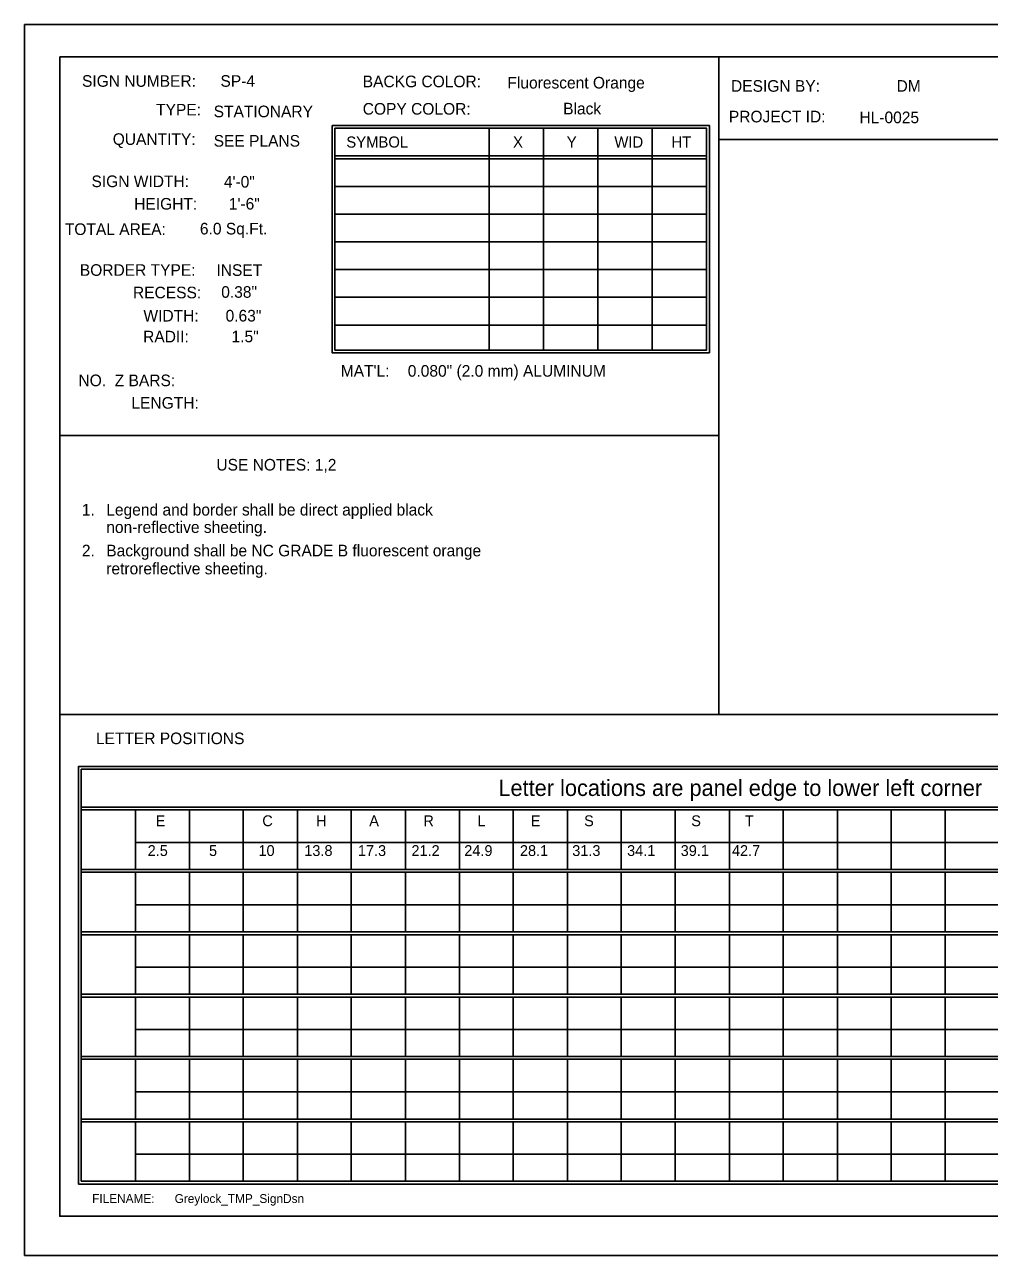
# Model space of a CAD drawing. Extents: x 1788.1 to 1851.2, y 237.2 to 283.4.
# Drawn here: x 1821.02 to 1837.36, y 237.17 to 258.03 of the extents above; entities that cross this region are included whole.
import ezdxf

# ---------------------------------------------------------------- set-up
doc = ezdxf.new("R2010")
doc.units = 0
for name, color, linetype in [('Old_Level_2', 7, 'Continuous'), ('Old_Level_3', 7, 'Continuous'), ('Old_Level_7', 7, 'Continuous'), ('Sheet Plot Border Outside CELL', 7, 'Continuous')]:
    doc.layers.add(name, color=color, linetype=linetype)

msp = doc.modelspace()

# ---------------------------------------------------------------- linework, layer by layer
at = {"layer": 'Old_Level_2'}
for p, q in [((1832.78, 257.479), (1832.78, 246.338)), ((1828.894, 256.27), (1828.894, 252.512)), ((1829.814, 256.27), (1829.814, 252.512)), ((1830.734, 256.27), (1830.734, 252.512)), ((1831.654, 256.27), (1831.654, 252.512)), ((1832.78, 256.081), (1849.944, 256.081)), ((1826.278, 255.8), (1832.575, 255.8)), ((1826.278, 255.754), (1832.575, 255.754)), ((1826.278, 255.284), (1832.575, 255.284)), ((1826.278, 254.814), (1832.575, 254.814)), ((1826.278, 254.344), (1832.575, 254.344)), ((1826.278, 253.875), (1832.575, 253.875)), ((1826.278, 253.405), (1832.575, 253.405)), ((1826.278, 252.935), (1832.575, 252.935)), ((1832.78, 251.061), (1821.618, 251.061)), ((1821.618, 246.338), (1832.78, 246.338)), ((1832.78, 246.338), (1849.944, 246.338)), ((1821.981, 244.765), (1843.759, 244.765)), ((1821.981, 244.719), (1843.759, 244.719)), ((1822.9, 244.719), (1822.9, 243.709)), ((1823.818, 244.719), (1823.818, 243.709)), ((1824.727, 244.719), (1824.727, 243.709)), ((1825.645, 244.719), (1825.645, 243.709)), ((1826.554, 244.719), (1826.554, 243.709)), ((1827.472, 244.719), (1827.472, 243.709)), ((1828.39, 244.719), (1828.39, 243.709)), ((1829.299, 244.719), (1829.299, 243.709)), ((1830.218, 244.719), (1830.218, 243.709)), ((1831.126, 244.719), (1831.126, 243.709)), ((1832.045, 244.719), (1832.045, 243.709)), ((1832.963, 244.719), (1832.963, 243.709)), ((1833.872, 244.719), (1833.872, 243.709)), ((1834.79, 244.719), (1834.79, 243.709)), ((1835.699, 244.719), (1835.699, 243.709)), ((1836.617, 244.719), (1836.617, 243.709)), ((1822.9, 244.168), (1843.759, 244.168)), ((1821.981, 243.709), (1843.759, 243.709)), ((1821.981, 243.663), (1843.759, 243.663)), ((1822.9, 243.663), (1822.9, 242.652)), ((1823.818, 243.663), (1823.818, 242.652)), ((1824.727, 243.663), (1824.727, 242.652)), ((1825.645, 243.663), (1825.645, 242.652)), ((1826.554, 243.663), (1826.554, 242.652)), ((1827.472, 243.663), (1827.472, 242.652)), ((1828.39, 243.663), (1828.39, 242.652)), ((1829.299, 243.663), (1829.299, 242.652)), ((1830.218, 243.663), (1830.218, 242.652)), ((1831.126, 243.663), (1831.126, 242.652)), ((1832.045, 243.663), (1832.045, 242.652)), ((1832.963, 243.663), (1832.963, 242.652)), ((1833.872, 243.663), (1833.872, 242.652)), ((1834.79, 243.663), (1834.79, 242.652)), ((1835.699, 243.663), (1835.699, 242.652)), ((1836.617, 243.663), (1836.617, 242.652)), ((1822.9, 243.112), (1843.759, 243.112)), ((1821.981, 242.652), (1843.759, 242.652)), ((1821.981, 242.606), (1843.759, 242.606)), ((1822.9, 242.606), (1822.9, 241.596)), ((1823.818, 242.606), (1823.818, 241.596)), ((1824.727, 242.606), (1824.727, 241.596)), ((1825.645, 242.606), (1825.645, 241.596)), ((1826.554, 242.606), (1826.554, 241.596)), ((1827.472, 242.606), (1827.472, 241.596)), ((1828.39, 242.606), (1828.39, 241.596)), ((1829.299, 242.606), (1829.299, 241.596)), ((1830.218, 242.606), (1830.218, 241.596)), ((1831.126, 242.606), (1831.126, 241.596)), ((1832.045, 242.606), (1832.045, 241.596)), ((1832.963, 242.606), (1832.963, 241.596)), ((1833.872, 242.606), (1833.872, 241.596)), ((1834.79, 242.606), (1834.79, 241.596)), ((1835.699, 242.606), (1835.699, 241.596)), ((1836.617, 242.606), (1836.617, 241.596)), ((1822.9, 242.055), (1843.759, 242.055)), ((1821.981, 241.596), (1843.759, 241.596)), ((1821.981, 241.55), (1843.759, 241.55)), ((1822.9, 241.55), (1822.9, 240.54)), ((1823.818, 241.55), (1823.818, 240.54)), ((1824.727, 241.55), (1824.727, 240.54)), ((1825.645, 241.55), (1825.645, 240.54)), ((1826.554, 241.55), (1826.554, 240.54)), ((1827.472, 241.55), (1827.472, 240.54)), ((1828.39, 241.55), (1828.39, 240.54)), ((1829.299, 241.55), (1829.299, 240.54)), ((1830.218, 241.55), (1830.218, 240.54)), ((1831.126, 241.55), (1831.126, 240.54)), ((1832.045, 241.55), (1832.045, 240.54)), ((1832.963, 241.55), (1832.963, 240.54)), ((1833.872, 241.55), (1833.872, 240.54)), ((1834.79, 241.55), (1834.79, 240.54)), ((1835.699, 241.55), (1835.699, 240.54)), ((1836.617, 241.55), (1836.617, 240.54)), ((1822.9, 240.999), (1843.759, 240.999)), ((1822.9, 240.657), (1822.9, 240.54)), ((1823.818, 240.657), (1823.818, 240.54)), ((1824.727, 240.657), (1824.727, 240.54)), ((1825.645, 240.657), (1825.645, 240.54)), ((1826.554, 240.657), (1826.554, 240.54)), ((1827.472, 240.657), (1827.472, 240.54)), ((1828.39, 240.657), (1828.39, 240.54)), ((1829.299, 240.657), (1829.299, 240.54)), ((1830.218, 240.657), (1830.218, 240.54)), ((1831.126, 240.657), (1831.126, 240.54)), ((1832.045, 240.657), (1832.045, 240.54)), ((1832.963, 240.657), (1832.963, 240.54)), ((1833.872, 240.657), (1833.872, 240.54)), ((1834.79, 240.657), (1834.79, 240.54)), ((1835.699, 240.657), (1835.699, 240.54)), ((1836.617, 240.657), (1836.617, 240.54)), ((1821.981, 240.54), (1843.759, 240.54)), ((1821.981, 240.54), (1843.759, 240.54)), ((1821.981, 240.494), (1843.759, 240.494)), ((1821.981, 240.494), (1843.759, 240.494)), ((1822.9, 240.494), (1822.9, 239.549)), ((1822.9, 240.494), (1822.9, 239.483)), ((1823.818, 240.494), (1823.818, 239.549)), ((1823.818, 240.494), (1823.818, 239.483)), ((1824.727, 240.494), (1824.727, 239.549)), ((1824.727, 240.494), (1824.727, 239.483)), ((1825.645, 240.494), (1825.645, 239.549)), ((1825.645, 240.494), (1825.645, 239.483)), ((1826.554, 240.494), (1826.554, 239.549)), ((1826.554, 240.494), (1826.554, 239.483)), ((1827.472, 240.494), (1827.472, 239.549)), ((1827.472, 240.494), (1827.472, 239.483)), ((1828.39, 240.494), (1828.39, 239.549)), ((1828.39, 240.494), (1828.39, 239.483)), ((1829.299, 240.494), (1829.299, 239.549)), ((1829.299, 240.494), (1829.299, 239.483)), ((1830.218, 240.494), (1830.218, 239.549)), ((1830.218, 240.494), (1830.218, 239.483)), ((1831.126, 240.494), (1831.126, 239.549)), ((1831.126, 240.494), (1831.126, 239.483)), ((1832.045, 240.494), (1832.045, 239.549)), ((1832.045, 240.494), (1832.045, 239.483)), ((1832.963, 240.494), (1832.963, 239.549)), ((1832.963, 240.494), (1832.963, 239.483)), ((1833.872, 240.494), (1833.872, 239.549)), ((1833.872, 240.494), (1833.872, 239.483)), ((1834.79, 240.494), (1834.79, 239.549)), ((1834.79, 240.494), (1834.79, 239.483)), ((1835.699, 240.494), (1835.699, 239.549)), ((1835.699, 240.494), (1835.699, 239.483)), ((1836.617, 240.494), (1836.617, 239.549)), ((1836.617, 240.494), (1836.617, 239.483)), ((1822.9, 239.942), (1843.759, 239.942)), ((1822.9, 239.942), (1843.759, 239.942)), ((1821.981, 239.483), (1843.759, 239.483)), ((1821.981, 239.483), (1843.759, 239.483)), ((1821.981, 239.437), (1843.759, 239.437)), ((1821.981, 239.437), (1843.759, 239.437)), ((1822.9, 239.601), (1822.9, 239.483)), ((1822.9, 239.437), (1822.9, 238.427)), ((1822.9, 239.437), (1822.9, 238.427)), ((1823.818, 239.601), (1823.818, 239.483)), ((1823.818, 239.437), (1823.818, 238.427)), ((1823.818, 239.437), (1823.818, 238.427)), ((1824.727, 239.601), (1824.727, 239.483)), ((1824.727, 239.437), (1824.727, 238.427)), ((1824.727, 239.437), (1824.727, 238.427)), ((1825.645, 239.601), (1825.645, 239.483)), ((1825.645, 239.437), (1825.645, 238.427)), ((1825.645, 239.437), (1825.645, 238.427)), ((1826.554, 239.601), (1826.554, 239.483)), ((1826.554, 239.437), (1826.554, 238.427)), ((1826.554, 239.437), (1826.554, 238.427)), ((1827.472, 239.601), (1827.472, 239.483)), ((1827.472, 239.437), (1827.472, 238.427)), ((1827.472, 239.437), (1827.472, 238.427)), ((1828.39, 239.601), (1828.39, 239.483)), ((1828.39, 239.437), (1828.39, 238.427)), ((1828.39, 239.437), (1828.39, 238.427)), ((1829.299, 239.601), (1829.299, 239.483)), ((1829.299, 239.437), (1829.299, 238.427)), ((1829.299, 239.437), (1829.299, 238.427)), ((1830.218, 239.601), (1830.218, 239.483)), ((1830.218, 239.437), (1830.218, 238.427)), ((1830.218, 239.437), (1830.218, 238.427)), ((1831.126, 239.601), (1831.126, 239.483)), ((1831.126, 239.437), (1831.126, 238.427)), ((1831.126, 239.437), (1831.126, 238.427)), ((1832.045, 239.601), (1832.045, 239.483)), ((1832.045, 239.437), (1832.045, 238.427)), ((1832.045, 239.437), (1832.045, 238.427)), ((1832.963, 239.601), (1832.963, 239.483)), ((1832.963, 239.437), (1832.963, 238.427)), ((1832.963, 239.437), (1832.963, 238.427)), ((1833.872, 239.601), (1833.872, 239.483)), ((1833.872, 239.437), (1833.872, 238.427)), ((1833.872, 239.437), (1833.872, 238.427)), ((1834.79, 239.601), (1834.79, 239.483)), ((1834.79, 239.437), (1834.79, 238.427)), ((1834.79, 239.437), (1834.79, 238.427)), ((1835.699, 239.601), (1835.699, 239.483)), ((1835.699, 239.437), (1835.699, 238.427)), ((1835.699, 239.437), (1835.699, 238.427)), ((1836.617, 239.601), (1836.617, 239.483)), ((1836.617, 239.437), (1836.617, 238.427)), ((1836.617, 239.437), (1836.617, 238.427)), ((1822.9, 238.886), (1843.759, 238.886)), ((1822.9, 238.886), (1843.759, 238.886)), ((1821.934, 238.381), (1843.759, 238.381)), ((1821.981, 238.427), (1843.759, 238.427)), ((1821.981, 238.427), (1843.759, 238.427)), ((1821.981, 238.381), (1843.759, 238.381))]:
    msp.add_line(p, q, dxfattribs=at)
for points in [[(1821.618, 257.479), (1849.944, 257.479), (1849.944, 237.834), (1821.618, 237.834)], [(1826.23, 256.318), (1832.623, 256.318), (1832.623, 252.465), (1826.23, 252.465)], [(1826.278, 256.27), (1832.575, 256.27), (1832.575, 252.512), (1826.278, 252.512)]]:
    msp.add_lwpolyline(points, close=True, dxfattribs=at)
for points in [[(1821.934, 239.549), (1821.934, 245.454), (1843.759, 245.454)], [(1821.981, 239.549), (1821.981, 245.408), (1843.759, 245.408)], [(1821.934, 238.381), (1821.934, 240.657)], [(1821.981, 238.427), (1821.981, 240.657)]]:
    msp.add_lwpolyline(points, dxfattribs=at)
at = {"layer": 'Sheet Plot Border Outside CELL'}
msp.add_lwpolyline([(1851.194, 258.025), (1821.023, 258.025), (1821.023, 237.172), (1851.194, 237.172)], close=True, dxfattribs=at)

# ---------------------------------------------------------------- texts
at = {"layer": 'Old_Level_2'}
for s, height, p in [('SIGN NUMBER:', 0.19685, (1821.995, 256.972)), ('BACKG COLOR:', 0.19685, (1826.75, 256.964)), ('DESIGN BY:', 0.1969, (1832.988, 256.888)), ('TYPE:', 0.1969, (1823.25, 256.486)), ('COPY COLOR:', 0.19685, (1826.75, 256.5)), ('PROJECT ID:', 0.19685, (1832.952, 256.369)), ('QUANTITY:', 0.1969, (1822.515, 255.987)), ('SIGN WIDTH:', 0.19685, (1822.155, 255.272)), ('HEIGHT:', 0.1969, (1822.879, 254.891)), ('TOTAL AREA:', 0.19685, (1821.704, 254.461)), ('BORDER TYPE:', 0.19685, (1821.958, 253.769)), ('RECESS:', 0.1969, (1822.858, 253.388)), ('WIDTH:', 0.1969, (1823.035, 252.995)), ('RADII:', 0.1969, (1823.03, 252.641)), ("MAT'L:", 0.1969, (1826.378, 252.06)), ('NO.  Z BARS:', 0.19685, (1821.935, 251.899)), ('LENGTH:', 0.1969, (1822.832, 251.518)), ('USE NOTES: 1,2', 0.19685, (1824.271, 250.47)), ('1.', 0.1969, (1821.993, 249.708)), ('Legend and border shall be direct applied black      ', 0.19685, (1822.406, 249.708)), ('2.', 0.1969, (1821.993, 249.016)), ('LETTER POSITIONS', 0.19685, (1822.23, 245.834)), ('Letter locations are panel edge to lower left corner', 0.27559, (1829.048, 244.956))]:
    msp.add_text(s, height=height, rotation=360, dxfattribs=at).set_placement(p)
for s, height, p in [('DM', 0.1969, (1835.793, 256.888)), ('HL-0025', 0.1969, (1835.164, 256.355)), ('SYMBOL', 0.1879, (1826.472, 255.942)), ('X', 0.188, (1829.296, 255.942)), ('Y', 0.188, (1830.206, 255.942)), ('WID', 0.1879, (1831.013, 255.942)), ('HT', 0.1879, (1831.979, 255.942)), ('0.080" (2.0 mm) ALUMINUM', 0.19685, (1827.513, 252.06)), ('non-reflective sheeting.', 0.19685, (1822.406, 249.413)), ('Background shall be NC GRADE B fluorescent orange', 0.19685, (1822.406, 249.016)), ('retroreflective sheeting.', 0.19685, (1822.406, 248.711)), ('E', 0.184, (1823.243, 244.444)), ('C', 0.184, (1825.049, 244.444)), ('H', 0.184, (1825.961, 244.444)), ('A', 0.184, (1826.86, 244.444)), ('R', 0.184, (1827.777, 244.444)), ('L', 0.184, (1828.693, 244.444)), ('E', 0.184, (1829.596, 244.444)), ('S', 0.184, (1830.5, 244.444)), ('S', 0.184, (1832.315, 244.444)), ('T', 0.184, (1833.223, 244.444)), ('2.5', 0.1837, (1823.107, 243.939)), ('5', 0.184, (1824.146, 243.939)), ('10', 0.1837, (1824.984, 243.939)), ('13.8', 0.1837, (1825.76, 243.939)), ('17.3', 0.1837, (1826.668, 243.939)), ('21.2', 0.1837, (1827.575, 243.939)), ('24.9', 0.1837, (1828.47, 243.939)), ('28.1', 0.1837, (1829.413, 243.939)), ('31.3', 0.1837, (1830.299, 243.939)), ('34.1', 0.1837, (1831.228, 243.939)), ('39.1', 0.1837, (1832.136, 243.939)), ('42.7', 0.1837, (1833.004, 243.939))]:
    msp.add_text(s, height=height, dxfattribs=at).set_placement(p)
at = {"layer": 'Old_Level_3'}
for s, height, p in [('SP-4', 0.1969, (1824.34, 256.972)), ('Fluorescent Orange', 0.19685, (1829.201, 256.943)), ('STATIONARY', 0.1969, (1824.225, 256.456)), ('SEE PLANS', 0.1969, (1824.225, 255.958)), ('4\'-0"', 0.1969, (1824.398, 255.264)), ('1\'-6"', 0.1969, (1824.482, 254.892)), ('6.0 Sq.Ft.', 0.1969, (1823.992, 254.47)), ('INSET', 0.1969, (1824.272, 253.768)), ('0.38"', 0.1969, (1824.353, 253.397)), ('0.63"', 0.1969, (1824.427, 252.995)), ('1.5"', 0.1969, (1824.528, 252.644))]:
    msp.add_text(s, height=height, rotation=360, dxfattribs=at).set_placement(p)
msp.add_text('Black', height=0.1969, dxfattribs=at).set_placement((1830.145, 256.504))
at = {"layer": 'Old_Level_7'}
for s, height, p in [('FILENAME:', 0.1497, (1822.167, 238.06)), ('Greylock_TMP_SignDsn', 0.14974, (1823.564, 238.06))]:
    msp.add_text(s, height=height, rotation=360, dxfattribs=at).set_placement(p)

doc.saveas('drawing.dxf')
